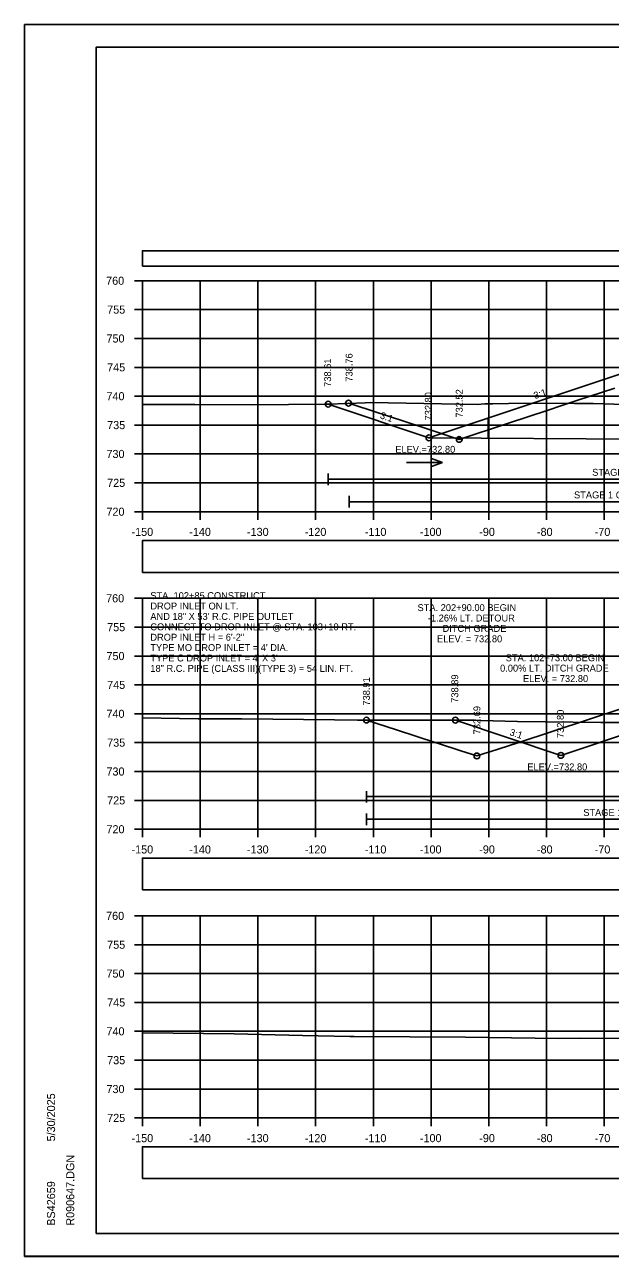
# Model space of a CAD drawing. Extents: x 1202951 to 1376887, y 378065 to 728038.
# Drawn here: x 1376414.3 to 1376515.7, y 378621.2 to 378834.5 of the extents above; entities that cross this region are included whole.
import ezdxf

# ---------------------------------------------------------------- set-up
doc = ezdxf.new("R2010")
doc.units = 0
for name, color, linetype in [('Default', 7, 'Continuous'), ('R_Alt Surface', 7, 'Continuous'), ('R_Axis', 7, 'Continuous'), ('R_Axis Annot', 7, 'Continuous'), ('R_Border', 7, 'Continuous'), ('R_Border Notes', 7, 'Continuous'), ('R_Detour', 7, 'Continuous'), ('R_Detour Annot', 7, 'Continuous'), ('R_Dimension', 7, 'Continuous'), ('R_Exist Surface', 7, 'Continuous'), ('R_Fin Surface', 7, 'Continuous'), ('R_Grid', 7, 'Continuous'), ('R_No Plot', 7, 'Continuous'), ('R_Proposed Const Limits', 7, 'Continuous'), ('R_Water', 7, 'Continuous'), ('R_Water Annot', 7, 'Continuous'), ('R_Xsect Elev', 7, 'Continuous'), ('R_Xsect Slope', 7, 'Continuous')]:
    doc.layers.add(name, color=color, linetype=linetype)

msp = doc.modelspace()

# ---------------------------------------------------------------- linework, layer by layer
at = {"layer": 'Default'}
for points in [[(1376547.67, 378776.42), (1376521.29, 378774.95), (1376520.29, 378774.95), (1376484.29, 378762.95)], [(1376547.67, 378721.46), (1376546.64, 378721.12), (1376546.64, 378721.12), (1376507.16, 378707.95)]]:
    msp.add_lwpolyline(points, dxfattribs=at)
at = {"layer": 'R_Alt Surface'}
for points in [[(1376434.67, 378792.65), (1376710.2, 378792.65), (1376710.2, 378795.36), (1376434.67, 378795.36)], [(1376434.67, 378739.63), (1376536.14, 378739.63), (1376536.14, 378745.15), (1376434.67, 378745.15)], [(1376434.67, 378684.63), (1376536.14, 378684.63), (1376536.14, 378690.15), (1376434.67, 378690.15)], [(1376434.67, 378634.63), (1376536.14, 378634.63), (1376536.14, 378640.15), (1376434.67, 378640.15)]]:
    msp.add_lwpolyline(points, close=True, dxfattribs=at)
at = {"layer": 'R_Axis'}
for p, q in [((1376433.27, 378790.15), (1376434.67, 378790.15)), ((1376434.67, 378750.15), (1376434.67, 378790.15)), ((1376433.27, 378785.15), (1376434.67, 378785.15)), ((1376433.27, 378780.15), (1376434.67, 378780.15)), ((1376433.27, 378775.15), (1376434.67, 378775.15)), ((1376433.27, 378770.15), (1376434.67, 378770.15)), ((1376433.27, 378765.15), (1376434.67, 378765.15)), ((1376433.27, 378760.15), (1376434.67, 378760.15)), ((1376433.27, 378755.15), (1376434.67, 378755.15)), ((1376433.27, 378750.15), (1376434.67, 378750.15)), ((1376434.67, 378750.15), (1376734.67, 378750.15)), ((1376434.67, 378748.75), (1376434.67, 378750.15)), ((1376444.67, 378748.75), (1376444.67, 378750.15)), ((1376454.67, 378748.75), (1376454.67, 378750.15)), ((1376464.67, 378748.75), (1376464.67, 378750.15)), ((1376474.67, 378748.75), (1376474.67, 378750.15)), ((1376484.67, 378748.75), (1376484.67, 378750.15)), ((1376494.67, 378748.75), (1376494.67, 378750.15)), ((1376504.67, 378748.75), (1376504.67, 378750.15)), ((1376514.67, 378748.75), (1376514.67, 378750.15)), ((1376433.27, 378735.15), (1376434.67, 378735.15)), ((1376434.67, 378695.15), (1376434.67, 378735.15)), ((1376433.27, 378730.15), (1376434.67, 378730.15)), ((1376433.27, 378725.15), (1376434.67, 378725.15)), ((1376433.27, 378720.15), (1376434.67, 378720.15)), ((1376433.27, 378715.15), (1376434.67, 378715.15)), ((1376433.27, 378710.15), (1376434.67, 378710.15)), ((1376433.27, 378705.15), (1376434.67, 378705.15)), ((1376433.27, 378700.15), (1376434.67, 378700.15)), ((1376433.27, 378695.15), (1376434.67, 378695.15)), ((1376434.67, 378695.15), (1376734.67, 378695.15)), ((1376434.67, 378693.75), (1376434.67, 378695.15)), ((1376444.67, 378693.75), (1376444.67, 378695.15)), ((1376454.67, 378693.75), (1376454.67, 378695.15)), ((1376464.67, 378693.75), (1376464.67, 378695.15)), ((1376474.67, 378693.75), (1376474.67, 378695.15)), ((1376484.67, 378693.75), (1376484.67, 378695.15)), ((1376494.67, 378693.75), (1376494.67, 378695.15)), ((1376504.67, 378693.75), (1376504.67, 378695.15)), ((1376514.67, 378693.75), (1376514.67, 378695.15)), ((1376433.27, 378680.15), (1376434.67, 378680.15)), ((1376434.67, 378645.15), (1376434.67, 378680.15)), ((1376433.27, 378675.15), (1376434.67, 378675.15)), ((1376433.27, 378670.15), (1376434.67, 378670.15)), ((1376433.27, 378665.15), (1376434.67, 378665.15)), ((1376433.27, 378660.15), (1376434.67, 378660.15)), ((1376433.27, 378655.15), (1376434.67, 378655.15)), ((1376433.27, 378650.15), (1376434.67, 378650.15)), ((1376433.27, 378645.15), (1376434.67, 378645.15)), ((1376434.67, 378645.15), (1376734.67, 378645.15)), ((1376434.67, 378643.75), (1376434.67, 378645.15)), ((1376444.67, 378643.75), (1376444.67, 378645.15)), ((1376454.67, 378643.75), (1376454.67, 378645.15)), ((1376464.67, 378643.75), (1376464.67, 378645.15)), ((1376474.67, 378643.75), (1376474.67, 378645.15)), ((1376484.67, 378643.75), (1376484.67, 378645.15)), ((1376494.67, 378643.75), (1376494.67, 378645.15)), ((1376504.67, 378643.75), (1376504.67, 378645.15)), ((1376514.67, 378643.75), (1376514.67, 378645.15))]:
    msp.add_line(p, q, dxfattribs=at)
at = {"layer": 'R_Border'}
for p, q in [((1376426.67, 378830.61), (1376742.85, 378830.61)), ((1376426.67, 378625.15), (1376426.67, 378830.61)), ((1376426.67, 378625.15), (1376426.67, 378625.15)), ((1376742.85, 378625.15), (1376426.67, 378625.15))]:
    msp.add_line(p, q, dxfattribs=at)
at = {"layer": 'R_Detour'}
for points in [[(1376470.36, 378768.95), (1376471.47, 378768.59), (1376483.27, 378764.73), (1376489.55, 378762.67), (1376498.06, 378765.48), (1376504.77, 378767.69), (1376507.51, 378768.59), (1376509.92, 378769.39), (1376516.5, 378771.55)], [(1376473.46, 378714.06), (1376478.66, 378712.37), (1376485.56, 378710.13), (1376485.65, 378710.1), (1376485.8, 378710.05), (1376489.8, 378708.75), (1376492.61, 378707.84), (1376494.76, 378708.54), (1376494.82, 378708.56), (1376499.67, 378710.13), (1376518.05, 378716.16)]]:
    msp.add_lwpolyline(points, dxfattribs=at)
at = {"layer": 'R_Dimension'}
for points in [[(1376466.85, 378756.77), (1376466.85, 378754.77)], [(1376466.85, 378755.8), (1376578.77, 378755.8)], [(1376470.46, 378752.87), (1376470.46, 378750.87)], [(1376470.46, 378751.87), (1376568.65, 378751.87)], [(1376473.46, 378701.77), (1376473.46, 378699.77)], [(1376473.46, 378700.8), (1376578.47, 378700.8)], [(1376473.46, 378697.87), (1376473.46, 378695.87)], [(1376473.46, 378696.87), (1376568.83, 378696.87)]]:
    msp.add_lwpolyline(points, dxfattribs=at)
at = {"layer": 'R_Exist Surface'}
for points in [[(1376434.67, 378768.71), (1376443.73, 378768.7), (1376453.65, 378768.67), (1376466.27, 378768.75), (1376466.77, 378768.76), (1376470.2, 378768.91), (1376473.23, 378769.03), (1376474.16, 378769.04), (1376492.63, 378768.74), (1376493.97, 378768.86), (1376495.36, 378768.85), (1376500.79, 378768.97), (1376509.5, 378768.91), (1376512.74, 378768.87), (1376525.23, 378768.46)], [(1376434.67, 378714.43), (1376444.31, 378714.25), (1376451.91, 378714.25), (1376467.96, 378714.1), (1376471.93, 378714.06), (1376490.22, 378714.05), (1376491.95, 378714.02), (1376492.18, 378714.04), (1376493.26, 378713.99), (1376499.63, 378713.8), (1376514.06, 378713.62), (1376517.74, 378713.61)], [(1376434.67, 378659.88), (1376450.58, 378659.71), (1376462.42, 378659.44), (1376470.6, 378659.27), (1376471.34, 378659.27), (1376490.63, 378659.14), (1376494.5, 378659.08), (1376506.82, 378658.91), (1376510.56, 378658.95), (1376523.06, 378658.9)]]:
    msp.add_lwpolyline(points, dxfattribs=at)
at = {"layer": 'R_Fin Surface'}
for points in [[(1376466.85, 378768.77), (1376484.29, 378762.95), (1376520.29, 378774.95), (1376521.29, 378774.95), (1376533.31, 378775.49), (1376547.18, 378776.26), (1376547.67, 378776.42), (1376552.67, 378776.32), (1376555.67, 378776.26), (1376556.16, 378776.26), (1376556.17, 378775.76), (1376557.17, 378775.78), (1376584.67, 378776.33), (1376601.17, 378776), (1376602.17, 378775.98), (1376602.18, 378776.48), (1376602.67, 378776.48), (1376605.67, 378776.54), (1376610.67, 378776.64), (1376612.25, 378776.11), (1376615, 378775.2)], [(1376488.87, 378714.05), (1376507.16, 378707.95), (1376546.64, 378721.12), (1376547.67, 378721.46), (1376552.67, 378721.36), (1376555.67, 378721.3), (1376556.16, 378721.3), (1376556.17, 378720.8), (1376557.17, 378720.82), (1376584.67, 378721.37), (1376601.17, 378721.04), (1376602.17, 378721.02), (1376602.18, 378721.52), (1376602.67, 378721.52), (1376605.67, 378721.58), (1376610.67, 378721.68), (1376612.25, 378721.15), (1376615.69, 378720.01)]]:
    msp.add_lwpolyline(points, dxfattribs=at)
at = {"layer": 'R_Grid'}
for p, q in [((1376434.67, 378790.15), (1376734.67, 378790.15)), ((1376434.67, 378750.15), (1376434.67, 378790.15)), ((1376444.67, 378750.15), (1376444.67, 378790.15)), ((1376454.67, 378750.15), (1376454.67, 378790.15)), ((1376464.67, 378750.15), (1376464.67, 378790.15)), ((1376474.67, 378750.15), (1376474.67, 378790.15)), ((1376484.67, 378750.15), (1376484.67, 378790.15)), ((1376494.67, 378750.15), (1376494.67, 378790.15)), ((1376504.67, 378750.15), (1376504.67, 378790.15)), ((1376514.67, 378750.15), (1376514.67, 378790.15)), ((1376434.67, 378785.15), (1376734.67, 378785.15)), ((1376434.67, 378780.15), (1376734.67, 378780.15)), ((1376434.67, 378775.15), (1376734.67, 378775.15)), ((1376434.67, 378770.15), (1376734.67, 378770.15)), ((1376434.67, 378765.15), (1376734.67, 378765.15)), ((1376434.67, 378760.15), (1376734.67, 378760.15)), ((1376434.67, 378755.15), (1376734.67, 378755.15)), ((1376434.67, 378750.15), (1376734.67, 378750.15)), ((1376434.67, 378735.15), (1376734.67, 378735.15)), ((1376434.67, 378695.15), (1376434.67, 378735.15)), ((1376444.67, 378695.15), (1376444.67, 378735.15)), ((1376454.67, 378695.15), (1376454.67, 378735.15)), ((1376464.67, 378695.15), (1376464.67, 378735.15)), ((1376474.67, 378695.15), (1376474.67, 378735.15)), ((1376484.67, 378695.15), (1376484.67, 378735.15)), ((1376494.67, 378695.15), (1376494.67, 378735.15)), ((1376504.67, 378695.15), (1376504.67, 378735.15)), ((1376514.67, 378695.15), (1376514.67, 378735.15)), ((1376434.67, 378730.15), (1376734.67, 378730.15)), ((1376434.67, 378725.15), (1376734.67, 378725.15)), ((1376434.67, 378720.15), (1376734.67, 378720.15)), ((1376434.67, 378715.15), (1376734.67, 378715.15)), ((1376434.67, 378710.15), (1376734.67, 378710.15)), ((1376434.67, 378705.15), (1376734.67, 378705.15)), ((1376434.67, 378700.15), (1376734.67, 378700.15)), ((1376434.67, 378695.15), (1376734.67, 378695.15)), ((1376434.67, 378680.15), (1376734.67, 378680.15)), ((1376434.67, 378645.15), (1376434.67, 378680.15)), ((1376444.67, 378645.15), (1376444.67, 378680.15)), ((1376454.67, 378645.15), (1376454.67, 378680.15)), ((1376464.67, 378645.15), (1376464.67, 378680.15)), ((1376474.67, 378645.15), (1376474.67, 378680.15)), ((1376484.67, 378645.15), (1376484.67, 378680.15)), ((1376494.67, 378645.15), (1376494.67, 378680.15)), ((1376504.67, 378645.15), (1376504.67, 378680.15)), ((1376514.67, 378645.15), (1376514.67, 378680.15)), ((1376434.67, 378675.15), (1376734.67, 378675.15)), ((1376434.67, 378670.15), (1376734.67, 378670.15)), ((1376434.67, 378665.15), (1376734.67, 378665.15)), ((1376434.67, 378660.15), (1376734.67, 378660.15)), ((1376434.67, 378655.15), (1376734.67, 378655.15)), ((1376434.67, 378650.15), (1376734.67, 378650.15)), ((1376434.67, 378645.15), (1376734.67, 378645.15))]:
    msp.add_line(p, q, dxfattribs=at)
at = {"layer": 'R_No Plot'}
for p, q in [((1376414.27, 378834.51), (1376747.6, 378834.51)), ((1376414.27, 378621.18), (1376747.6, 378621.18))]:
    msp.add_line(p, q, dxfattribs=at)
for points in [[(1376414.26, 378834.51), (1376747.6, 378834.51), (1376747.6, 378621.17), (1376414.26, 378621.17)], [(1376660.59, 378830.61), (1376680.21, 378830.61), (1376680.21, 378820.73), (1376696.32, 378820.73), (1376719.52, 378820.73), (1376719.64, 378792.58), (1376742.85, 378792.58), (1376742.85, 378625.15), (1376426.67, 378625.15), (1376426.67, 378830.61)]]:
    msp.add_lwpolyline(points, close=True, dxfattribs=at)
for centre in [(1376466.85, 378768.77), (1376466.85, 378768.77), (1376470.36, 378768.95), (1376484.29, 378762.95), (1376484.29, 378762.95), (1376489.55, 378762.67), (1376489.55, 378762.67), (1376473.46, 378714.06), (1376488.87, 378714.05), (1376488.87, 378714.05), (1376507.16, 378707.95), (1376507.16, 378707.95), (1376492.61, 378707.84), (1376492.61, 378707.84)]:
    msp.add_circle(centre, 0.5, dxfattribs=at)
at = {"layer": 'R_Proposed Const Limits'}
for points in [[(1376484.29, 378762.95), (1376466.85, 378768.77)], [(1376507.16, 378707.95), (1376488.87, 378714.05)]]:
    msp.add_lwpolyline(points, dxfattribs=at)
at = {"layer": 'R_Water'}
for p, q in [((1376494.54, 378766.47), (1376494.54, 378762.88)), ((1376524.67, 378762.67), (1376484.29, 378762.95))]:
    msp.add_line(p, q, dxfattribs=at)
at = {"layer": 'R_Water Annot'}
for p, q in [((1376480.39, 378758.67), (1376486.67, 378758.67)), ((1376486.67, 378758.67), (1376484.75, 378759.37)), ((1376486.67, 378758.67), (1376484.75, 378757.97))]:
    msp.add_line(p, q, dxfattribs=at)

# ---------------------------------------------------------------- texts
at = {"layer": 'R_Axis Annot'}
for s, p in [('760', (1376428.38, 378789.45)), ('755', (1376428.56, 378784.45)), ('750', (1376428.44, 378779.45)), ('745', (1376428.56, 378774.45)), ('740', (1376428.44, 378769.45)), ('735', (1376428.56, 378764.45)), ('730', (1376428.44, 378759.45)), ('725', (1376428.56, 378754.45)), ('720', (1376428.44, 378749.45)), ('-150', (1376432.78, 378745.95)), ('-140', (1376442.78, 378745.95)), ('-130', (1376452.78, 378745.95)), ('-120', (1376462.78, 378745.95)), ('-110', (1376473.18, 378745.95)), ('-100', (1376482.73, 378745.95)), ('-90', (1376493.01, 378745.95)), ('-80', (1376503.01, 378745.95)), ('-70', (1376513.01, 378745.95)), ('760', (1376428.38, 378734.45)), ('755', (1376428.56, 378729.45)), ('750', (1376428.44, 378724.45)), ('745', (1376428.56, 378719.45)), ('740', (1376428.44, 378714.45)), ('735', (1376428.56, 378709.45)), ('730', (1376428.44, 378704.45)), ('725', (1376428.56, 378699.45)), ('720', (1376428.44, 378694.45)), ('-150', (1376432.78, 378690.95)), ('-140', (1376442.78, 378690.95)), ('-130', (1376452.78, 378690.95)), ('-120', (1376462.78, 378690.95)), ('-110', (1376473.18, 378690.95)), ('-100', (1376482.73, 378690.95)), ('-90', (1376493.01, 378690.95)), ('-80', (1376503.01, 378690.95)), ('-70', (1376513.01, 378690.95)), ('760', (1376428.38, 378679.45)), ('755', (1376428.56, 378674.45)), ('750', (1376428.44, 378669.45)), ('745', (1376428.56, 378664.45)), ('740', (1376428.44, 378659.45)), ('735', (1376428.56, 378654.45)), ('730', (1376428.44, 378649.45)), ('725', (1376428.56, 378644.45)), ('-150', (1376432.78, 378640.95)), ('-140', (1376442.78, 378640.95)), ('-130', (1376452.78, 378640.95)), ('-120', (1376462.78, 378640.95)), ('-110', (1376473.18, 378640.95)), ('-100', (1376482.73, 378640.95)), ('-90', (1376493.01, 378640.95)), ('-80', (1376503.01, 378640.95)), ('-70', (1376513.01, 378640.95))]:
    msp.add_text(s, height=1.4, dxfattribs=at).set_placement(p)
at = {"layer": 'R_Border'}
for s, p in [('5/30/2025', (1376419.54, 378641.08)), ('R090647.DGN', (1376422.86, 378626.48)), ('BS42659', (1376419.54, 378626.48))]:
    msp.add_text(s, height=1.4, rotation=90, dxfattribs=at).set_placement(p)
at = {"layer": 'R_Border Notes'}
for s, p in [('ELEV.=732.80', (1376478.46, 378760.35)), ('STA. 102+73.00 BEGIN', (1376497.6, 378724.25)), ('0.00% LT. DITCH GRADE', (1376496.62, 378722.45)), ('ELEV. = 732.80', (1376500.59, 378720.65)), ('ELEV.=732.80', (1376501.33, 378705.35))]:
    msp.add_text(s, height=1.2, dxfattribs=at).set_placement(p)
at = {"layer": 'R_Detour Annot'}
for s, p in [('738.76', (1376471.06, 378772.67)), ('732.52', (1376490.15, 378766.46)), ('738.91', (1376474.06, 378716.56)), ('732.69', (1376493.21, 378711.59))]:
    msp.add_text(s, height=1.2, rotation=90, dxfattribs=at).set_placement(p)
for s, p in [('STA. 202+90.00 BEGIN', (1376482.32, 378732.93)), ('-1.26% LT. DETOUR', (1376484.11, 378731.13)), ('DITCH GRADE', (1376486.66, 378729.33)), ('ELEV. = 732.80', (1376485.7, 378727.53))]:
    msp.add_text(s, height=1.2, dxfattribs=at).set_placement(p)
at = {"layer": 'R_Dimension'}
for s, p in [('STAGE 3 CONSTRUCTION', (1376512.57, 378756.37)), ('STAGE 1 CONSTRUCTION', (1376509.43, 378752.45)), ('STAGE 1 CONSTRUCTION', (1376511.03, 378697.45))]:
    msp.add_text(s, height=1.2, dxfattribs=at).set_placement(p)
at = {"layer": 'R_Water Annot'}
for s, p in [('STA. 102+85 CONSTRUCT', (1376436.04, 378735.01)), ('DROP INLET ON LT.', (1376436.04, 378733.21)), ('AND 18" X 53\' R.C. PIPE OUTLET', (1376436.04, 378731.41)), ('CONNECT TO DROP INLET @ STA. 103+10 RT.', (1376436.04, 378729.61)), ('DROP INLET H = 6\'-2"', (1376436.04, 378727.81)), ("TYPE MO DROP INLET = 4' DIA.", (1376436.04, 378726.01)), ("TYPE C DROP INLET = 4' X 3' ", (1376436.04, 378724.21)), ('18" R.C. PIPE (CLASS III)(TYPE 3) = 54 LIN. FT.', (1376436.04, 378722.41))]:
    msp.add_text(s, height=1.2, dxfattribs=at).set_placement(p)
at = {"layer": 'R_Xsect Elev'}
for s, p in [('738.61', (1376467.35, 378771.77)), ('738.61', (1376467.35, 378771.77)), ('732.80', (1376484.79, 378765.95)), ('732.80', (1376484.79, 378765.95)), ('738.89', (1376489.37, 378717.05)), ('738.89', (1376489.37, 378717.05)), ('732.80', (1376507.66, 378710.95)), ('732.80', (1376507.66, 378710.95))]:
    msp.add_text(s, height=1.2, rotation=90, dxfattribs=at).set_placement(p)
at = {"layer": 'R_Xsect Slope'}
for rotation, p in [(18.4349, (1376502.66, 378769.64)), (341.5651, (1376475.73, 378766.34)), (341.5651, (1376498.17, 378711.48))]:
    msp.add_text('3:1', height=1.2, rotation=rotation, dxfattribs=at).set_placement(p)

doc.saveas('drawing.dxf')
